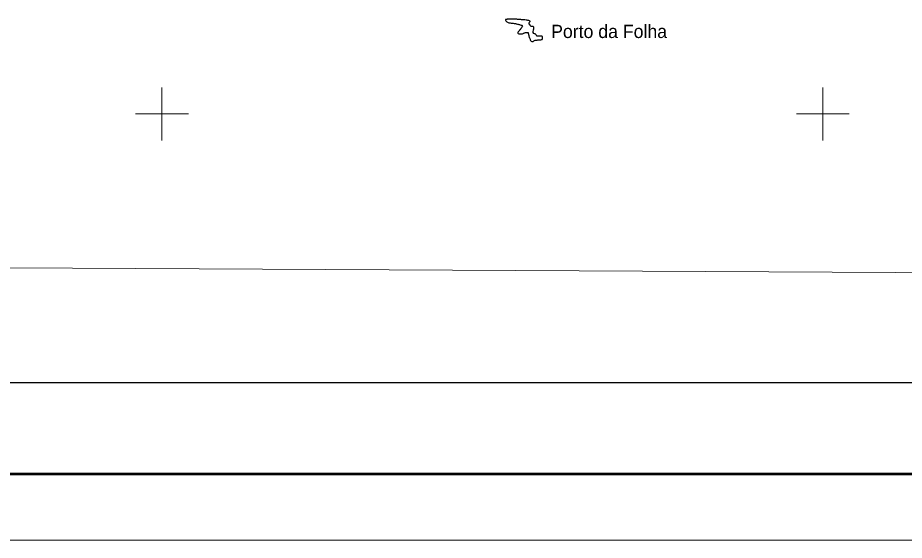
# Model space of a CAD drawing. Extents: x 553962 to 842807, y 8883888 to 9032388.
# Drawn here: x 669542 to 703083, y 8883888 to 8903636 of the extents above; entities that cross this region are included whole.
import ezdxf

# ---------------------------------------------------------------- set-up
doc = ezdxf.new("R2010")
doc.units = 0
doc.header["$LTSCALE"] = 160
for name, color, linetype, lineweight in [('1', 7, 'Continuous', 13), ('2', 7, 'Continuous', 13), ('28', 7, 'Continuous', 13)]:
    doc.layers.add(name, color=color, linetype=linetype, lineweight=lineweight)
doc.layers.add('29', color=7, linetype='Continuous')

msp = doc.modelspace()

# ---------------------------------------------------------------- linework, layer by layer
at = {"layer": '1'}
for p, q in [((675000, 8899000), (675000, 8901000)), ((700000, 8899000), (700000, 8901000)), ((674000, 8900000), (676000, 8900000)), ((699000, 8900000), (701000, 8900000))]:
    msp.add_line(p, q, dxfattribs=at)
msp.add_lwpolyline([(842807.3, 9032387.8), (842807.3, 8883887.8), (553961.7, 8883887.8), (553961.7, 9032387.8)], close=True, dxfattribs=at)
at = {"layer": '1', "lineweight": 53}
msp.add_lwpolyline([(840307.3, 9029887.8), (840307.3, 8886387.8), (560211.7, 8886387.8), (560211.7, 9029887.8)], close=True, dxfattribs=at)
at = {"layer": '1', "lineweight": 25}
msp.add_lwpolyline([(563033.9, 9026438.8), (793061.1, 9026438.8), (793495.6, 8889836.8), (563468.3, 8889836.8)], close=True, dxfattribs=at)
at = {"layer": '2'}
msp.add_lwpolyline([(564751.7, 8894587.5), (664411.9, 8894209.9), (791388.5, 8893536.2)], dxfattribs=at)
at = {"layer": '28'}
for points in [[(687999.3, 8903568.5), (688042.6, 8903573.7), (688065.5, 8903578.8), (688085.8, 8903581.3), (688111.3, 8903586.4), (688131.6, 8903586.4), (688162.2, 8903589), (688197.8, 8903589), (688218.1, 8903589), (688251.2, 8903589), (688281.8, 8903589), (688319.9, 8903586.4), (688363.2, 8903583.9), (688386.1, 8903581.3), (688424.2, 8903578.8), (688454.8, 8903573.7), (688490.4, 8903573.7), (688510.8, 8903571.1), (688536.2, 8903568.6), (688556.6, 8903568.6), (688576.9, 8903566), (688602.4, 8903563.4), (688632.9, 8903560.9), (688666, 8903558.3), (688701.6, 8903555.8), (688722, 8903553.2), (688783, 8903545.6), (688818.7, 8903540.4), (688841.6, 8903537.9), (688861.9, 8903532.8), (688882.3, 8903527.7), (688905.2, 8903517.4), (688925.5, 8903509.8), (688925.5, 8903489.3), (688905.2, 8903471.4), (688895, 8903440.8), (688887.4, 8903420.3), (688895, 8903397.3), (688915.4, 8903376.8), (688928.1, 8903348.7), (688943.4, 8903328.3), (688961.2, 8903307.8), (688984.1, 8903307.8), (689009.6, 8903307.8), (689045.2, 8903300.2), (689068.1, 8903282.3), (689068.1, 8903251.6), (689065.6, 8903231.2), (689065.6, 8903210.7), (689055.4, 8903190.2), (689052.9, 8903167.2), (689037.6, 8903118.7), (689037.6, 8903098.2), (689045.3, 8903077.8), (689068.2, 8903047.1), (689093.6, 8903034.3), (689116.5, 8903024.1), (689139.5, 8903006.2), (689154.7, 8902985.8), (689164.9, 8902965.3), (689185.3, 8902942.3), (689208.2, 8902942.3), (689233.6, 8902942.3), (689254, 8902944.9), (689282, 8902944.9), (689307.4, 8902944.9), (689332.8, 8902944.9), (689365.9, 8902939.8), (689396.5, 8902921.9), (689396.5, 8902886.1), (689396.5, 8902858), (689396.5, 8902837.5), (689383.8, 8902817.1), (689358.3, 8902811.9), (689338, 8902804.3), (689317.6, 8902801.7), (689287.1, 8902799.2), (689266.8, 8902799.2), (689243.8, 8902799.2), (689213.3, 8902796.6), (689193, 8902794.1), (689165, 8902791.5), (689142.1, 8902788.9), (689116.6, 8902783.8), (689093.7, 8902773.6), (689068.3, 8902758.3), (689037.8, 8902740.4), (689017.4, 8902740.4), (688994.5, 8902742.9), (688964, 8902755.7), (688943.6, 8902778.7), (688933.4, 8902804.3), (688923.2, 8902827.3), (688915.6, 8902852.8), (688905.4, 8902873.3), (688895.2, 8902893.7), (688895.2, 8902914.2), (688885, 8902939.7), (688877.4, 8902975.5), (688872.3, 8902996), (688867.2, 8903019)], [(688867.2, 8903019), (688857, 8903054.8), (688849.4, 8903075.2), (688826.5, 8903077.8), (688806.1, 8903077.8), (688775.6, 8903077.8), (688752.7, 8903075.2), (688732.3, 8903067.6), (688706.9, 8903062.4), (688684, 8903054.8), (688663.6, 8903044.5), (688635.6, 8903034.3), (688615.3, 8903029.2), (688587.3, 8903026.7), (688556.8, 8903026.7), (688531.3, 8903026.7), (688500.8, 8903029.2), (688480.4, 8903036.9), (688457.5, 8903054.8), (688462.6, 8903077.8), (688475.3, 8903098.2), (688490.6, 8903121.2), (688508.4, 8903146.8), (688531.3, 8903167.2), (688551.6, 8903185.1), (688556.7, 8903205.6), (688577.1, 8903218.4), (688584.7, 8903238.8), (688605, 8903254.2), (688617.7, 8903279.7), (688633, 8903300.2), (688643.2, 8903320.6), (688633, 8903346.2), (688612.6, 8903356.4), (688584.6, 8903361.5), (688556.6, 8903366.6), (688528.6, 8903376.8), (688495.6, 8903381.9), (688475.2, 8903392.2), (688452.3, 8903399.8), (688416.7, 8903407.5), (688396.3, 8903412.6), (688368.3, 8903417.7), (688348, 8903420.3), (688322.5, 8903422.8), (688286.9, 8903425.4), (688264, 8903425.4), (688230.9, 8903430.5), (688208, 8903433.1), (688177.5, 8903438.2), (688154.6, 8903440.7), (688124.1, 8903448.4), (688091, 8903458.6), (688070.6, 8903471.4), (688050.2, 8903479.1), (688029.9, 8903499.5), (688007, 8903517.4), (687999.3, 8903543), (687999.3, 8903568.5)]]:
    msp.add_lwpolyline(points, dxfattribs=at)
at = {"layer": '28', "lineweight": 25}
for points in [[(688867.2, 8903019), (688872.3, 8902996), (688877.4, 8902975.5), (688885, 8902939.7), (688895.2, 8902914.2), (688895.2, 8902893.7), (688905.4, 8902873.3), (688915.6, 8902852.8), (688923.2, 8902827.3), (688933.4, 8902804.3), (688943.6, 8902778.7), (688964, 8902755.7), (688994.5, 8902742.9), (689017.4, 8902740.4), (689037.8, 8902740.4), (689068.3, 8902758.3), (689093.7, 8902773.6), (689116.6, 8902783.8), (689142.1, 8902788.9), (689165, 8902791.5), (689193, 8902794.1), (689213.3, 8902796.6), (689243.8, 8902799.2), (689266.8, 8902799.2), (689287.1, 8902799.2), (689317.6, 8902801.7), (689338, 8902804.3), (689358.3, 8902811.9), (689383.8, 8902817.1), (689396.5, 8902837.5), (689396.5, 8902858), (689396.5, 8902886.1), (689396.5, 8902921.9), (689365.9, 8902939.8), (689332.8, 8902944.9), (689307.4, 8902944.9), (689282, 8902944.9), (689254, 8902944.9), (689233.6, 8902942.3), (689208.2, 8902942.3), (689185.3, 8902942.3), (689164.9, 8902965.3), (689154.7, 8902985.8), (689139.5, 8903006.2), (689116.5, 8903024.1), (689093.6, 8903034.3), (689068.2, 8903047.1), (689045.3, 8903077.8), (689037.6, 8903098.2), (689037.6, 8903118.7), (689052.9, 8903167.2), (689055.4, 8903190.2), (689065.6, 8903210.7), (689065.6, 8903231.2), (689068.1, 8903251.6), (689068.1, 8903282.3), (689045.2, 8903300.2), (689009.6, 8903307.8), (688984.1, 8903307.8), (688961.2, 8903307.8), (688943.4, 8903328.3), (688928.1, 8903348.7), (688915.4, 8903376.8), (688895, 8903397.3), (688887.4, 8903420.3), (688895, 8903440.8), (688905.2, 8903471.4), (688925.5, 8903489.3), (688925.5, 8903509.8), (688905.2, 8903517.4), (688882.3, 8903527.7), (688861.9, 8903532.8), (688841.6, 8903537.9), (688818.7, 8903540.4), (688783, 8903545.6), (688722, 8903553.2), (688701.6, 8903555.8), (688666, 8903558.3), (688632.9, 8903560.9), (688602.4, 8903563.4), (688576.9, 8903566), (688556.6, 8903568.6), (688536.2, 8903568.6), (688510.8, 8903571.1), (688490.4, 8903573.7), (688454.8, 8903573.7), (688424.2, 8903578.8), (688386.1, 8903581.3), (688363.2, 8903583.9), (688319.9, 8903586.4), (688281.8, 8903589), (688251.2, 8903589), (688218.1, 8903589), (688197.8, 8903589), (688162.2, 8903589), (688131.6, 8903586.4), (688111.3, 8903586.4), (688085.8, 8903581.3), (688065.5, 8903578.8), (688042.6, 8903573.7), (687999.3, 8903568.5)], [(687999.3, 8903568.5), (687999.3, 8903543), (688007, 8903517.4), (688029.9, 8903499.5), (688050.2, 8903479.1), (688070.6, 8903471.4), (688091, 8903458.6), (688124.1, 8903448.4), (688154.6, 8903440.7), (688177.5, 8903438.2), (688208, 8903433.1), (688230.9, 8903430.5), (688264, 8903425.4), (688286.9, 8903425.4), (688322.5, 8903422.8), (688348, 8903420.3), (688368.3, 8903417.7), (688396.3, 8903412.6), (688416.7, 8903407.5), (688452.3, 8903399.8), (688475.2, 8903392.2), (688495.6, 8903381.9), (688528.6, 8903376.8), (688556.6, 8903366.6), (688584.6, 8903361.5), (688612.6, 8903356.4), (688633, 8903346.2), (688643.2, 8903320.6), (688633, 8903300.2), (688617.7, 8903279.7), (688605, 8903254.2), (688584.7, 8903238.8), (688577.1, 8903218.4), (688556.7, 8903205.6), (688551.6, 8903185.1), (688531.3, 8903167.2), (688508.4, 8903146.8), (688490.6, 8903121.2), (688475.3, 8903098.2), (688462.6, 8903077.8), (688457.5, 8903054.8), (688480.4, 8903036.9), (688500.8, 8903029.2), (688531.3, 8903026.7), (688556.8, 8903026.7), (688587.3, 8903026.7), (688615.3, 8903029.2), (688635.6, 8903034.3), (688663.6, 8903044.5), (688684, 8903054.8), (688706.9, 8903062.4), (688732.3, 8903067.6), (688752.7, 8903075.2), (688775.6, 8903077.8), (688806.1, 8903077.8), (688826.5, 8903077.8), (688849.4, 8903075.2), (688857, 8903054.8), (688867.2, 8903019)]]:
    msp.add_lwpolyline(points, dxfattribs=at)

# ---------------------------------------------------------------- texts
at = {"layer": '29'}
msp.add_text('Porto da Folha', height=500, dxfattribs=at).set_placement((689722.9, 8902870))

doc.saveas('drawing.dxf')
